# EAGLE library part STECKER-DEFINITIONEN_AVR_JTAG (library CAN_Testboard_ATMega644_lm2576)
AVR JTAG Adapter Zum Programmieren/Simulieren von AVRs in der Schaltung
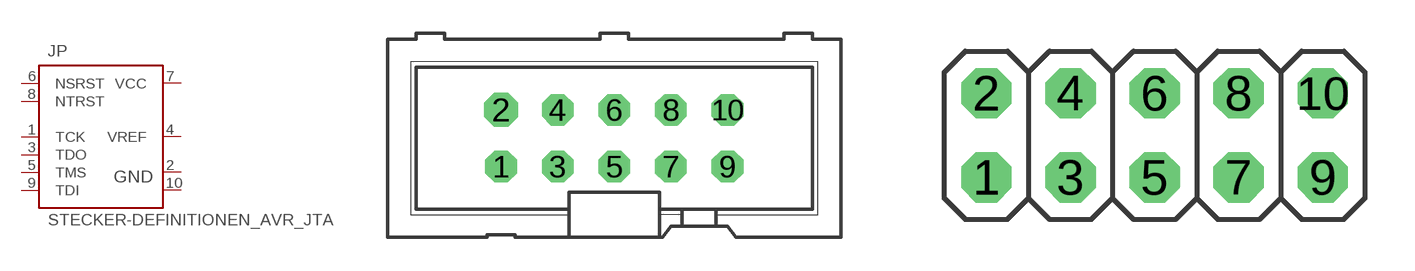
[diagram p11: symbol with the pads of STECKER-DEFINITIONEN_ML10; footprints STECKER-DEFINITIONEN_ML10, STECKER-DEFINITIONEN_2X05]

Designator prefix JP

## STECKER-DEFINITIONEN_AVR_JTAG  [STECKER-DEFINITIONEN_ML10]
1  TCK
2  GND  pwr
3  TDO
4  VREF  in
5  TMS
6  NSRST
7  VCC  pwr
8  NTRST
9  TDI
10  GND  pwr

## STECKER-DEFINITIONEN_AVR_JTAGS  [STECKER-DEFINITIONEN_2X05]
Pads as for STECKER-DEFINITIONEN_ML10

## STECKER-DEFINITIONEN_AVR_JTAGV  [STECKER-DEFINITIONEN_ML10L]
Pads as for STECKER-DEFINITIONEN_ML10

## Footprint STECKER-DEFINITIONEN_ML10 (pad centres in mm)
HARTING
drill 0.914 pad 1.422 octagon: 1 -5.08,-1.27; 3 -2.54,-1.27; 4 -2.54,1.27
drill 1.016 pad 1.422 octagon: 2 -5.08,1.27
drill 0.914 octagon: 5 0,-1.27; 6 0,1.27; 7 2.54,-1.27; 8 2.54,1.27; 9 5.08,-1.27; 10 5.08,1.27

## Footprint STECKER-DEFINITIONEN_2X05 (pad centres in mm)
PIN HEADER
drill 1.016 octagon: 1 -5.08,-1.27; 2 -5.08,1.27; 3 -2.54,-1.27; 4 -2.54,1.27; 5 0,-1.27; 6 0,1.27; 7 2.54,-1.27; 8 2.54,1.27; 9 5.08,-1.27; 10 5.08,1.27

## Footprint STECKER-DEFINITIONEN_ML10L (pad centres in mm)
HARTING
drill 0.914 octagon: 1 -5.08,-1.27; 2 -5.08,1.27; 3 -2.54,-1.27; 4 -2.54,1.27; 5 0,-1.27; 6 0,1.27; 7 2.54,-1.27; 8 2.54,1.27; 9 5.08,-1.27; 10 5.08,1.27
